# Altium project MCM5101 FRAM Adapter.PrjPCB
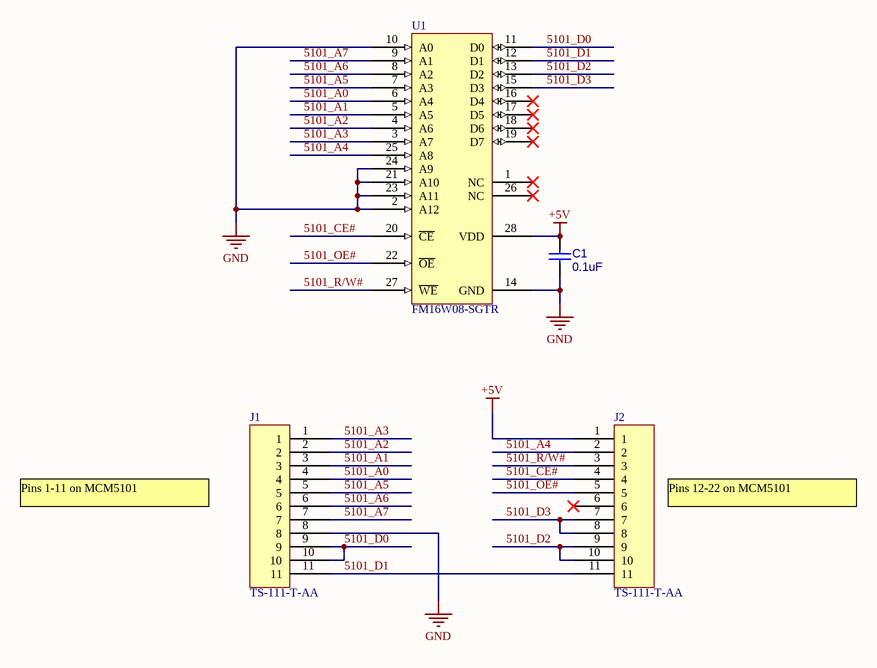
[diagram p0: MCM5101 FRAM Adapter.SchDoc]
1 sheet, 4 parts. Net scope: global (net labels, ports and power ports of the same name join across sheets).
Board file: MCM5101 FRAM Adapter.PcbDoc

## Sheet MCM5101 FRAM Adapter.SchDoc
size B

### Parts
C1  0.1uF  [CC0603]
J1  TS-111-T-AA  [Samtec_TS-111-XX]
J2  TS-111-T-AA  [Samtec_TS-111-XX]
U1  FM16W08-SGTR  [SOIC127P1030X264-28N]

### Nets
+5V: C1.2 J2.1 U1.28(VDD)
GND: C1.1 J1.8 U1.2(A12) U1.10(A0) U1.14(GND) U1.21(A10) U1.23(A11) U1.24(A9)
5101_A0: J1.4 U1.6(A4)
5101_A1: J1.3 U1.5(A5)
5101_A2: J1.2 U1.4(A6)
5101_A3: J1.1 U1.3(A7)
5101_A4: J2.2 U1.25(A8)
5101_A5: J1.5 U1.7(A3)
5101_A6: J1.6 U1.8(A2)
5101_A7: J1.7 U1.9(A1)
5101_CE#: J2.4 U1.20(~{CE})
5101_D0: J1.9 J1.10 U1.11(D0)
5101_D1: J1.11 J2.11 U1.12(D1)
5101_D2: J2.9 J2.10 U1.13(D2)
5101_D3: J2.7 J2.8 U1.15(D3)
5101_OE#: J2.5 U1.22(~{OE})
5101_R/W#: J2.3 U1.27(~{WE})

Not connected (* = marked no-connect by the designer): J2 6*; U1 1(NC)* 16(D4)* 17(D5)* 18(D6)* 19(D7)* 26(NC)*

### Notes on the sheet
- Pins 1-11 on MCM5101
- Pins 12-22 on MCM5101

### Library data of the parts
C1 = 0.1uF,10V,CC0603,X7R,+/-20%: 0.1uF 10V, in a CC0603, X7R ,+/-20%,LF; Manufacturer: Kemet; PartNumber: C0603C104M8RAC; Voltage: 10; Designator: C?; Component Subkind: Capacitor; Approved: Pending
J1 J2 = Samtec_TS-111-T-AA: PRECISION MACHINED TERMINAL STRIP, 0.018" diameter post; Manufacturer: Samtec
U1 = FM16W08-SGTR: IC FRAM 64KBIT (8Kx8) 70NS 28SOIC; Manufacturer: Ramtron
